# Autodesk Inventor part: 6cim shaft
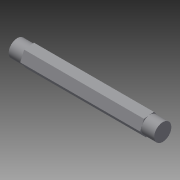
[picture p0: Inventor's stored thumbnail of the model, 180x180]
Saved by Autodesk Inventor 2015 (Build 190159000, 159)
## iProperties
Created: 2014-11
Part Number: 6cim shaft
Material: Generic
Document SubType Name: Modeling
Designer: User
Density: 1 g/cm^3
Appearance: Default
Author: User
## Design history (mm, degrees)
sketch "Sketch1"
  geometry: L1 (40.45, 0)-(40.45, 4.763); L2 (40.45, 4.763)-(33.325, 4.762); L3 (33.325, 4.762)-(33.325, 12.7); L4 (33.325, 12.7)-(-33.325, 12.7); L5 (-33.325, 12.7)-(-33.325, 4.762); L6 (-33.325, 4.762)-(-40.45, 4.763); L7 (-40.45, 4.763)-(-40.45, 0); L8 (0, 12.7)-(0, 0); L9 (-40.45, 0)-(40.45, 0)
  constraints: 18 end point, 5 perpendicular, 2 horizontal alignment, 2 point on line, 2 vertical, 1 collinear, 1 horizontal, 1 midpoint
  dimensions: "d0" = 12.7 distance from line of L8.end L4; "d1" = 66.6496 distance between parallel lines of L3 L5 (= hexLength); "d2" = 4.7625 distance from line of L8.end L2; "d3" = 80.899 distance between parallel lines of L7 L1 (= hexLength + bearingShaftLength)
revolve "Revolution1" sketch "Sketch1" stored, may be unused: angle "d4" = 90 deg
sketch "Sketch2"
  geometry: L1 (-3.288, 4.408)-(2.174, 5.051); L2 (2.174, 5.051)-(5.462, 0.643); L3 (5.462, 0.643)-(3.288, -4.408); L4 (3.288, -4.408)-(-2.174, -5.051); L5 (-2.174, -5.051)-(-5.462, -0.643); L6 (-5.462, -0.643)-(-3.288, 4.408); C1 r 4.763 at (0, 0) reference; C2 r 4.763 at (0, 0) reference; C3 r 4.762 at (0, 0) reference; C4 r 12.7 at (0, 0) reference; 2 further points
  constraints: 12 end point, 1 coincident, 1 tangent, 13 other
extrude "Extrusion1" cut sketch "Sketch2" distance "d5" = 66.6496 (= hexLength); taper "d6" = 0 deg
body "Solid1"
node "Projected Loop1"
node "Projected Loop2"
other parameters: "hexLength" = 66.6496 [user parameter; used in 3 equation terms], "bearingShaftLength" = 14.2494 [user parameter; used in 1 equation term]
